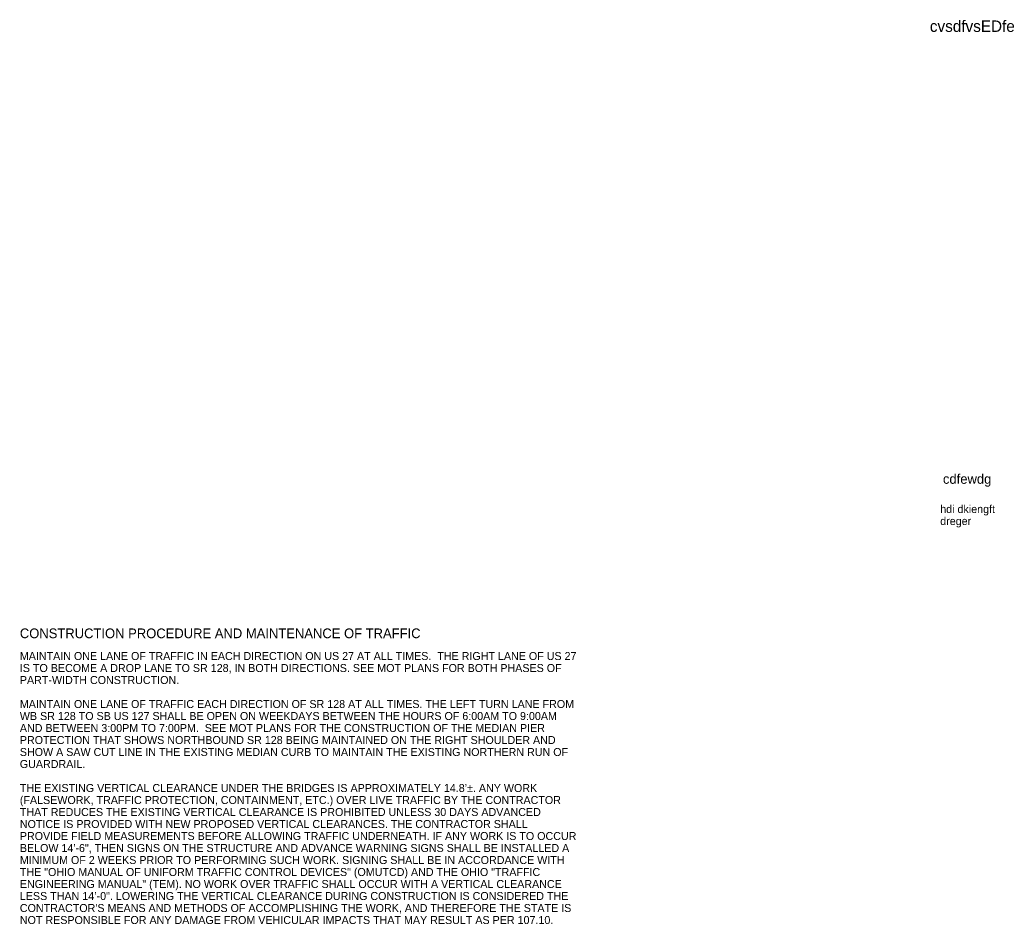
# Model space of a CAD drawing. Extents: x -17.8 to 35.4, y -13.8 to 33.2.
# Drawn here: x -17.76 to -0.37, y 5.08 to 20.9 of the extents above; entities that cross this region are included whole.
import ezdxf

# ---------------------------------------------------------------- set-up
doc = ezdxf.new("R2010")
doc.units = 0
doc.layers.add('BR_P_Gen_Text', color=7, linetype='Continuous')

msp = doc.modelspace()

# ---------------------------------------------------------------- texts
at = {"layer": 'BR_P_Gen_Text'}
for s, height, p in [('cvsdfvsEDfe', 0.2, (-1.841, 20.689)), ('cdfewdg', 0.17, (-1.612, 12.781)), ('hdi dkiengft', 0.14, (-1.659, 12.269)), ('dreger', 0.14, (-1.659, 12.059))]:
    msp.add_text(s, height=height, dxfattribs=at).set_placement(p)
for s, height, p in [('CONSTRUCTION PROCEDURE AND MAINTENANCE OF TRAFFIC', 0.17, (-17.759, 10.079)), ('MAINTAIN ONE LANE OF TRAFFIC IN EACH DIRECTION ON US 27 AT ALL TIMES.  THE RIGHT LANE OF US 27 ', 0.14, (-17.759, 9.697)), ('IS TO BECOME A DROP LANE TO SR 128, IN BOTH DIRECTIONS. SEE MOT PLANS FOR BOTH PHASES OF ', 0.14, (-17.759, 9.487)), ('PART-WIDTH CONSTRUCTION.', 0.14, (-17.759, 9.277)), ('MAINTAIN ONE LANE OF TRAFFIC EACH DIRECTION OF SR 128 AT ALL TIMES. THE LEFT TURN LANE FROM ', 0.14, (-17.759, 8.857)), ('WB SR 128 TO SB US 127 SHALL BE OPEN ON WEEKDAYS BETWEEN THE HOURS OF 6:00AM TO 9:00AM ', 0.14, (-17.759, 8.647)), ('AND BETWEEN 3:00PM TO 7:00PM.  SEE MOT PLANS FOR THE CONSTRUCTION OF THE MEDIAN PIER ', 0.14, (-17.759, 8.437)), ('PROTECTION THAT SHOWS NORTHBOUND SR 128 BEING MAINTAINED ON THE RIGHT SHOULDER AND ', 0.14, (-17.759, 8.227)), ('SHOW A SAW CUT LINE IN THE EXISTING MEDIAN CURB TO MAINTAIN THE EXISTING NORTHERN RUN OF ', 0.14, (-17.759, 8.017)), ('GUARDRAIL.', 0.14, (-17.759, 7.807)), ('THE EXISTING VERTICAL CLEARANCE UNDER THE BRIDGES IS APPROXIMATELY 14.8’±. ANY WORK ', 0.14, (-17.759, 7.387)), ('(FALSEWORK, TRAFFIC PROTECTION, CONTAINMENT, ETC.) OVER LIVE TRAFFIC BY THE CONTRACTOR ', 0.14, (-17.759, 7.177)), ('THAT REDUCES THE EXISTING VERTICAL CLEARANCE IS PROHIBITED UNLESS 30 DAYS ADVANCED ', 0.14, (-17.759, 6.967)), ('NOTICE IS PROVIDED WITH NEW PROPOSED VERTICAL CLEARANCES. THE CONTRACTOR SHALL ', 0.14, (-17.759, 6.757)), ('PROVIDE FIELD MEASUREMENTS BEFORE ALLOWING TRAFFIC UNDERNEATH. IF ANY WORK IS TO OCCUR ', 0.14, (-17.759, 6.547)), ('BELOW 14\'-6", THEN SIGNS ON THE STRUCTURE AND ADVANCE WARNING SIGNS SHALL BE INSTALLED A ', 0.14, (-17.759, 6.337)), ('MINIMUM OF 2 WEEKS PRIOR TO PERFORMING SUCH WORK. SIGNING SHALL BE IN ACCORDANCE WITH ', 0.14, (-17.759, 6.127)), ('THE "OHIO MANUAL OF UNIFORM TRAFFIC CONTROL DEVICES" (OMUTCD) AND THE OHIO "TRAFFIC ', 0.14, (-17.759, 5.917)), ('ENGINEERING MANUAL" (TEM). NO WORK OVER TRAFFIC SHALL OCCUR WITH A VERTICAL CLEARANCE ', 0.14, (-17.759, 5.707)), ('LESS THAN 14’-0". LOWERING THE VERTICAL CLEARANCE DURING CONSTRUCTION IS CONSIDERED THE ', 0.14, (-17.759, 5.497)), ("CONTRACTOR'S MEANS AND METHODS OF ACCOMPLISHING THE WORK, AND THEREFORE THE STATE IS ", 0.14, (-17.759, 5.287)), ('NOT RESPONSIBLE FOR ANY DAMAGE FROM VEHICULAR IMPACTS THAT MAY RESULT AS PER 107.10.', 0.14, (-17.759, 5.077))]:
    msp.add_text(s, height=height, rotation=0, dxfattribs=at).set_placement(p)

doc.saveas('drawing.dxf')
